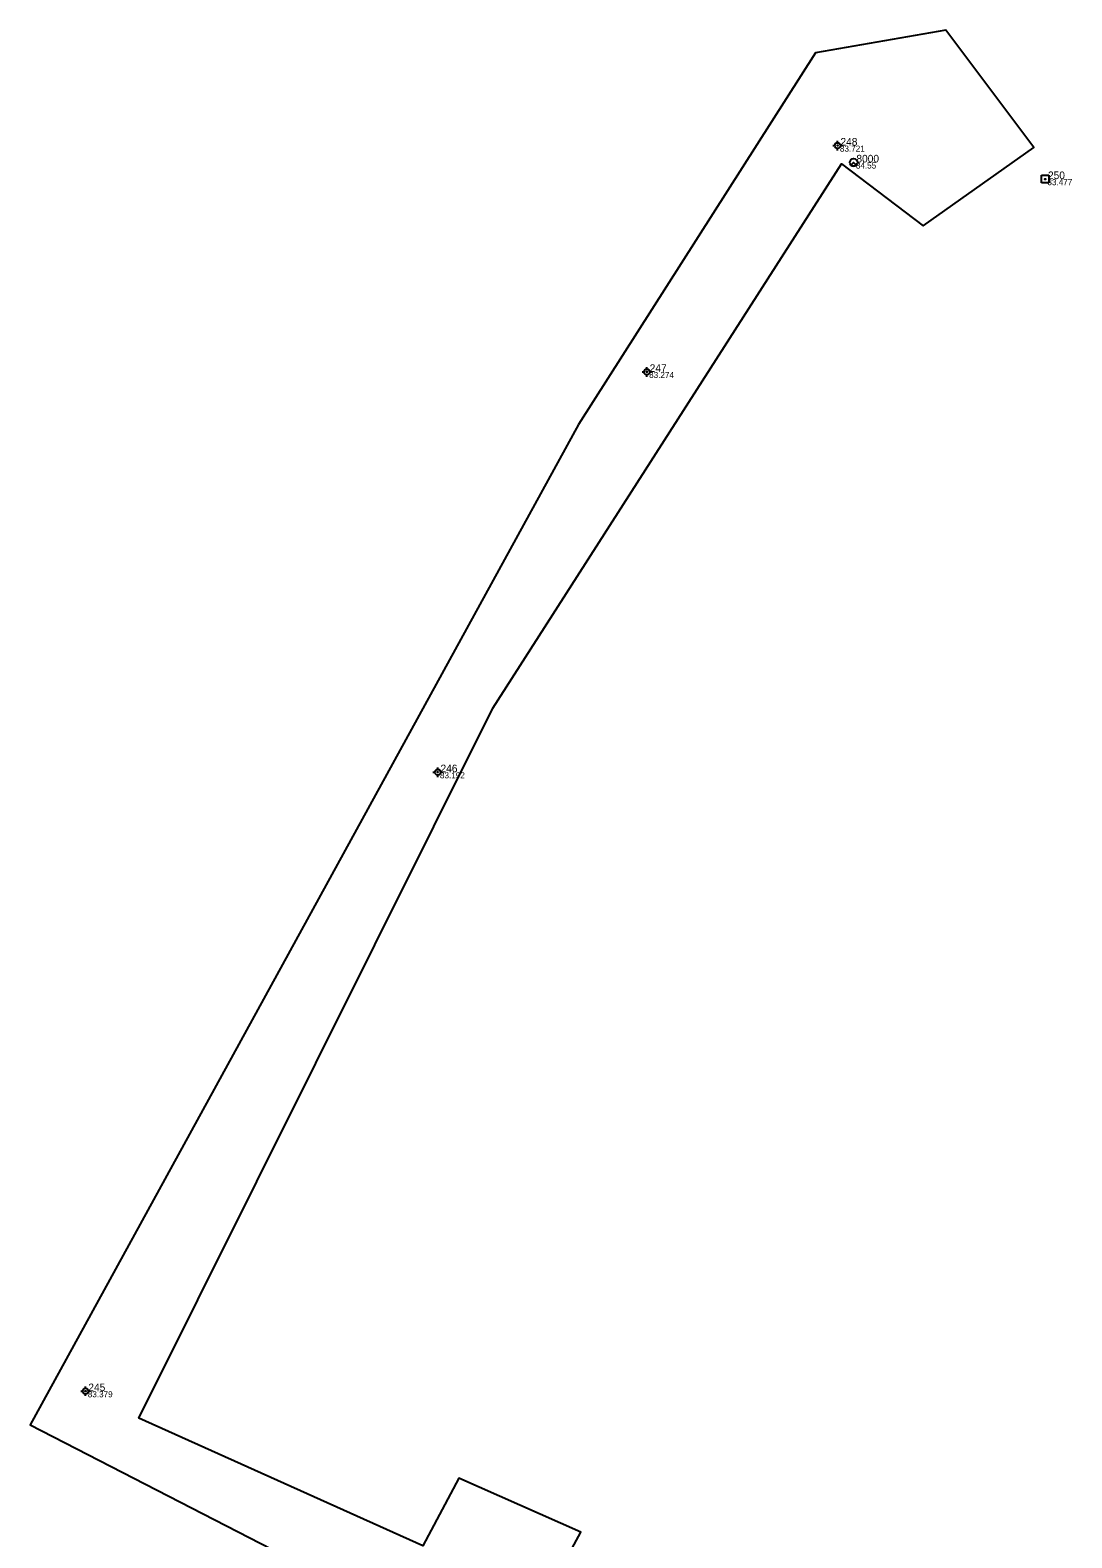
# Model space of a CAD drawing. Extents: x 614915 to 615767, y 262115 to 264410.
# Drawn here: x 614915.5 to 615052.6, y 262698.2 to 262896.6 of the extents above; entities that cross this region are included whole.
import ezdxf

# ---------------------------------------------------------------- set-up
doc = ezdxf.new("R2010")
doc.units = 0
doc.layers.add('Level 19', color=7, linetype='Continuous')
doc.layers.add('Level 25', color=7, linetype='Continuous')

msp = doc.modelspace()

# ---------------------------------------------------------------- linework, layer by layer
at = {"layer": 'Level 19'}
for p, q in [((615021.77, 262881.74), (615021.77, 262881.99)), ((615021.15, 262881.37), (615021.4, 262881.37)), ((615021.77, 262880.74), (615021.77, 262880.99)), ((615022.15, 262881.37), (615022.4, 262881.37)), ((615048.58, 262877.46), (615049.58, 262877.46)), ((615048.58, 262876.46), (615048.58, 262877.46)), ((615049.58, 262876.46), (615048.58, 262876.46)), ((615049.58, 262877.46), (615049.58, 262876.46)), ((614996.66, 262851.96), (614996.66, 262852.21)), ((614996.04, 262851.59), (614996.29, 262851.59)), ((614996.66, 262850.96), (614996.66, 262851.21)), ((614997.04, 262851.59), (614997.29, 262851.59)), ((614968.51, 262798.92), (614968.76, 262798.92)), ((614969.13, 262799.29), (614969.13, 262799.54)), ((614969.13, 262798.29), (614969.13, 262798.54)), ((614969.51, 262798.92), (614969.76, 262798.92)), ((614922.15, 262717.49), (614922.4, 262717.49)), ((614922.78, 262717.86), (614922.78, 262718.11)), ((614923.15, 262717.49), (614923.4, 262717.49)), ((614922.78, 262716.86), (614922.78, 262717.11))]:
    msp.add_line(p, q, dxfattribs=at)
msp.add_lwpolyline([(615024.22, 262878.79), (615023.87, 262879.15), (615023.51, 262878.79)], dxfattribs=at)
for centre, radius in [((615021.77, 262881.37), 0.375), ((615021.77, 262881.37), 0.05), ((615023.87, 262879.15), 0.499), ((615023.87, 262879.15), 0.499), ((615049.08, 262876.96), 0.05), ((614996.66, 262851.59), 0.375), ((614996.66, 262851.59), 0.05), ((614969.13, 262798.92), 0.375), ((614969.13, 262798.92), 0.05), ((614922.78, 262717.49), 0.375), ((614922.78, 262717.49), 0.05)]:
    msp.add_circle(centre, radius, dxfattribs=at)
msp.add_arc((615023.87, 262879.15), 0.499, 225, 315, dxfattribs=at)
at = {"layer": 'Level 25'}
msp.add_lwpolyline([(614983.1, 262689.95), (614987.95, 262698.96), (614971.93, 262706.04), (614967.17, 262697.13), (614929.81, 262713.94), (614976.39, 262807.36), (615022.29, 262878.97), (615033.02, 262870.83), (615047.61, 262881.12), (615036.02, 262896.56), (615018.86, 262893.55), (614987.68, 262844.67), (614915.49, 262713.06), (614965.53, 262687.34)], dxfattribs=at)

# ---------------------------------------------------------------- texts
at = {"layer": 'Level 19'}
for s, height, p in [(' 248', 1, (615021.77, 262881.37)), (' 83.721', 0.8, (615021.77, 262880.57)), (' 8000', 1, (615023.87, 262879.15)), (' rep', 0.3, (615023.87, 262878.85)), (' 84.55', 0.8, (615023.87, 262878.35)), (' 250', 1, (615049.08, 262876.96)), (' 83.477', 0.8, (615049.08, 262876.16)), (' 247', 1, (614996.66, 262851.59)), (' 83.274', 0.8, (614996.66, 262850.79)), (' 83.192', 0.8, (614969.13, 262798.12)), (' 246', 1, (614969.13, 262798.92)), (' 83.379', 0.8, (614922.78, 262716.69)), (' 245', 1, (614922.78, 262717.49))]:
    msp.add_text(s, height=height, dxfattribs=at).set_placement(p)

doc.saveas('drawing.dxf')
